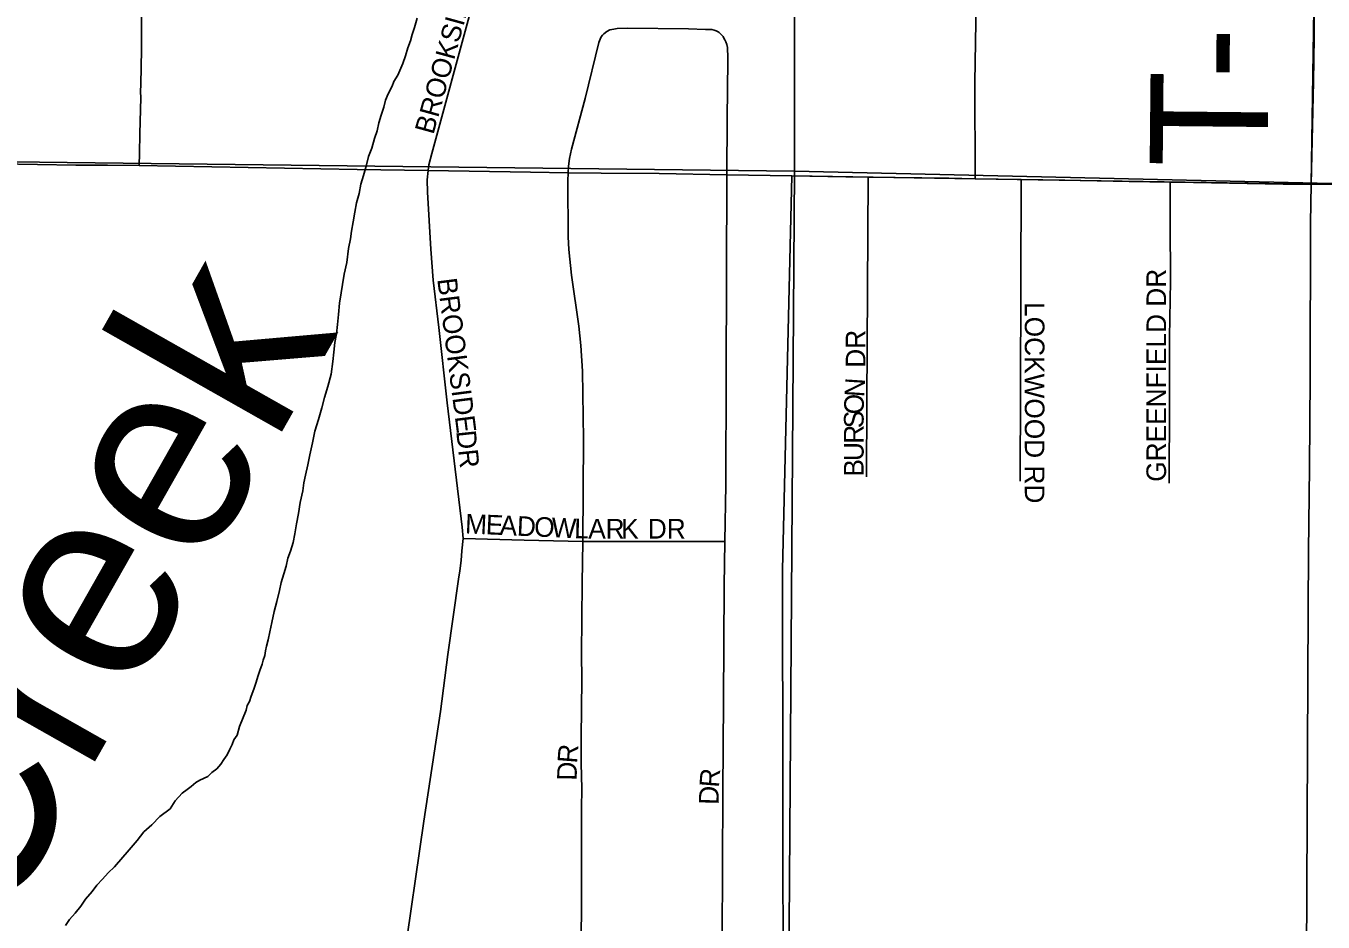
# Model space of a CAD drawing. Extents: x 1587405 to 1714697, y 1028970 to 1155083.
# Drawn here: x 1654205 to 1657507, y 1101017 to 1103299 of the extents above; entities that cross this region are included whole.
import ezdxf

# ---------------------------------------------------------------- set-up
doc = ezdxf.new("R2010")
doc.units = 0
for name, color, linetype in [('GM_X_City_Street', 7, 'Continuous'), ('GM_X_City_Street_Text', 7, 'Continuous'), ('GM_X_Corporation', 7, 'Continuous'), ('GM_X_County_Road', 7, 'Continuous'), ('GM_X_Minor_River', 7, 'Continuous'), ('GM_X_Minor_River_Text', 7, 'Continuous'), ('GM_X_Section', 7, 'Continuous'), ('GM_X_Township_Road', 7, 'Continuous'), ('GM_X_Township_Road_Text', 7, 'Continuous'), ('GM_X_Township_Subdivision', 7, 'Continuous'), ('GM_X_Township_Subdivision_Text', 7, 'Continuous')]:
    doc.layers.add(name, color=color, linetype=linetype)

msp = doc.modelspace()

# ---------------------------------------------------------------- linework, layer by layer
at = {"layer": 'GM_X_City_Street'}
for points in [[(1655228.4, 1102931.1), (1655230.8, 1102945.5), (1655238.5, 1102974), (1655336.1, 1103332.1), (1655370.9, 1103463.4), (1655425.8, 1103654.1)], [(1654493.3, 1102943.2), (1654493.8, 1102975.2), (1654494.5, 1103024), (1654497.1, 1103116.4), (1654496.2, 1103130.9), (1654497.5, 1103150.6), (1654499, 1103238), (1654499.3, 1103444)], [(1656621.7, 1102909.9), (1656620.9, 1103156.2), (1656624.4, 1103410.8)], [(1655989.2, 1102920), (1655989.7, 1103063.4), (1655992, 1103211.1), (1655991.6, 1103225.3), (1655991.2, 1103236.2), (1655990.5, 1103243.7), (1655989, 1103251.4), (1655986.4, 1103258.4), (1655984.4, 1103263.6), (1655981.8, 1103268.3), (1655979.9, 1103271.9), (1655976.7, 1103275.7), (1655972.6, 1103279.8), (1655969.7, 1103281.9), (1655966.9, 1103284.1), (1655962, 1103286.6), (1655956.5, 1103288.3), (1655951.2, 1103289.6), (1655948.6, 1103289.9), (1655942.2, 1103290.3), (1655934.5, 1103290.3), (1655891.2, 1103291.8), (1655736.4, 1103293.3), (1655709.8, 1103292.2), (1655701.7, 1103291.2), (1655691.7, 1103288.7), (1655683.7, 1103285.2), (1655676.1, 1103279.1)], [(1655585, 1102925.2), (1655586.2, 1102942.1), (1655589, 1102961.7), (1655593.8, 1102985.2), (1655628.6, 1103114.4), (1655663.1, 1103256.8), (1655666.5, 1103265.7), (1655669.6, 1103271.3), (1655673, 1103275.5), (1655676.1, 1103279.1)], [(1653516.3, 1102952.3), (1653676.5, 1102951.3), (1653922.3, 1102949.4), (1654135.5, 1102948.2), (1654332.1, 1102944.6), (1654412.6, 1102944.6), (1654493.3, 1102943.2)], [(1654493.3, 1102943.2), (1655047.8, 1102933.3), (1655228.4, 1102931.1)], [(1655228.4, 1102931.1), (1655226.4, 1102907.3), (1655226.9, 1102875.7), (1655235.7, 1102730.2), (1655241.9, 1102651.5), (1655256, 1102530.8), (1655277.5, 1102339.2), (1655315.1, 1102022.6), (1655317.6, 1101993.9)], [(1655228.4, 1102931.1), (1655489.3, 1102926.5), (1655585, 1102925.2)], [(1655622.8, 1101985.7), (1655624.6, 1102246.5), (1655621.6, 1102420.1), (1655617.7, 1102485.5), (1655612.3, 1102534.4), (1655593.7, 1102664.2), (1655586.7, 1102729.4), (1655585.2, 1102762.1), (1655584, 1102904.8), (1655585, 1102925.2)], [(1655585, 1102925.2), (1655669.6, 1102924), (1655817.2, 1102923.3), (1655989.2, 1102920)], [(1655984.1, 1101986.2), (1655986.6, 1102130), (1655987.8, 1102409.1), (1655989.2, 1102920)], [(1655989.2, 1102920), (1656154.5, 1102917.2)], [(1655317.6, 1101993.9), (1655314.8, 1101962.3), (1655312.6, 1101937.3), (1655309.3, 1101911.5), (1655306, 1101890.4), (1655278.5, 1101698.4), (1655260.4, 1101552.6), (1655217.7, 1101273.7), (1655164.7, 1100903.6)], [(1655317.6, 1101993.9), (1655473.6, 1101989.8), (1655622.8, 1101985.7)], [(1655614.4, 1100892), (1655618.8, 1101028.2), (1655618.8, 1101142.9), (1655618.8, 1101306.9), (1655619.7, 1101356.1), (1655618.3, 1101421.5), (1655618.4, 1101487), (1655619.9, 1101634.3), (1655619.4, 1101699.8), (1655620.6, 1101880.1), (1655622.8, 1101985.7)], [(1655622.8, 1101985.7), (1655984.1, 1101986.2)], [(1655975.7, 1100887.2), (1655977.3, 1100972), (1655978.9, 1101349.4), (1655980.4, 1101579.1), (1655982.1, 1101873.1), (1655984.1, 1101986.2)]]:
    msp.add_lwpolyline(points, dxfattribs=at)
at = {"layer": 'GM_X_Corporation'}
msp.add_lwpolyline([(1660013.6, 1108132.7), (1659992.5, 1104646), (1659461.1, 1104914.9), (1659349.2, 1104921.4), (1659344, 1103338.8), (1659336.3, 1102861.5), (1658982.8, 1102866.6), (1658983.7, 1102753.2), (1658842.9, 1102872.1), (1658419.8, 1103185), (1658402.9, 1103164.5), (1658418.3, 1103151.6), (1658415.7, 1103129.7), (1658127.5, 1103132.3), (1657841.9, 1103138.8), (1657848.8, 1103552), (1657490.3, 1103777.1), (1657484.7, 1103398.8), (1657477.2, 1102896.2), (1656621.6, 1102909.9), (1656154.5, 1102917.2), (1656130.9, 1101913.7), (1656133.6, 1100208.9)], dxfattribs=at)
at = {"layer": 'GM_X_County_Road'}
for points in [[(1656154.5, 1102917.2), (1656292.4, 1102914.8), (1656349, 1102913.9)], [(1656349, 1102913.9), (1656554.7, 1102911), (1656621.7, 1102909.9)], [(1656621.7, 1102909.9), (1656738.8, 1102907.8)], [(1656738.8, 1102907.8), (1656849.8, 1102905.9), (1657013.6, 1102902.9), (1657118, 1102901.3)], [(1657118, 1102901.3), (1657177.6, 1102900.3), (1657405.2, 1102896.2), (1657477.2, 1102896.2)], [(1657477.2, 1102896.2), (1657650.8, 1102893.4), (1657814.2, 1102889.6), (1658173.8, 1102884.2), (1658468.1, 1102878.7), (1658746, 1102871.9), (1658806.3, 1102872), (1658842.9, 1102872.1)]]:
    msp.add_lwpolyline(points, dxfattribs=at)
at = {"layer": 'GM_X_Minor_River'}
for points in [[(1655200.8, 1103318.8), (1655194.2, 1103294.9), (1655187.9, 1103276.9), (1655183.5, 1103261), (1655177.1, 1103243.1), (1655170.7, 1103223.1), (1655164.3, 1103203.2), (1655151.7, 1103173.3), (1655141.3, 1103157.5), (1655137, 1103145.6), (1655126.6, 1103125.7), (1655120.3, 1103109.8), (1655115.9, 1103091.8), (1655109.5, 1103071.9), (1655103, 1103052), (1655098.6, 1103032), (1655092.2, 1103012.1), (1655085.7, 1102988.1), (1655077.2, 1102966.2), (1655070.7, 1102942.3), (1655064.2, 1102918.3), (1655057.7, 1102896.4), (1655053.2, 1102872.4), (1655046.7, 1102848.5), (1655042.2, 1102824.5), (1655037.7, 1102800.5), (1655033.2, 1102776.5), (1655030.8, 1102756.5), (1655026.3, 1102732.5), (1655021.6, 1102696.5), (1655015, 1102666.6), (1655003.4, 1102592.6), (1655000.8, 1102564.5), (1654998.3, 1102538.5), (1654995.8, 1102514.5), (1654991.4, 1102492.5), (1654988.9, 1102468.5), (1654986.4, 1102444.5), (1654981.7, 1102412.5), (1654973, 1102380.5), (1654964.5, 1102352.6), (1654957.9, 1102326.7), (1654949.3, 1102296.8), (1654940.6, 1102266.8), (1654934, 1102236.9), (1654927.4, 1102206.9), (1654922.8, 1102180.9), (1654916.3, 1102155), (1654911.9, 1102135), (1654909.5, 1102115), (1654902.8, 1102085.1), (1654898.3, 1102057.1), (1654893.7, 1102031.1), (1654889.2, 1102005.1), (1654884.7, 1101983.1), (1654878.3, 1101961.2), (1654871.9, 1101943.2), (1654867.5, 1101923.3), (1654861, 1101903.3), (1654854.6, 1101881.4)], [(1654854.6, 1101881.4), (1654850.1, 1101861.4), (1654843.6, 1101833.5), (1654837, 1101807.5), (1654830.4, 1101779.6), (1654825.9, 1101755.6), (1654821.5, 1101735.6), (1654817.2, 1101719.7), (1654814.9, 1101707.7), (1654812.7, 1101695.7), (1654808.4, 1101683.7), (1654806.2, 1101673.8), (1654799.9, 1101657.8), (1654795.5, 1101641.9), (1654791.2, 1101627.9), (1654784.9, 1101610), (1654778.5, 1101592.1), (1654774.2, 1101578.1), (1654768, 1101568.2), (1654765.7, 1101556.2), (1654748.8, 1101514.4), (1654742.3, 1101492.5), (1654734.1, 1101480.6), (1654729.8, 1101468.7), (1654723.6, 1101456.8), (1654717.3, 1101442.8), (1654709, 1101431), (1654700.7, 1101419.1), (1654690.4, 1101407.3), (1654678.2, 1101397.5), (1654668, 1101387.7), (1654647.7, 1101378), (1654637.6, 1101372.2), (1654625.3, 1101362.4), (1654615.1, 1101354.6), (1654602.9, 1101344.8), (1654584.4, 1101325.2), (1654572, 1101305.3), (1654545.5, 1101285.8), (1654525, 1101264.2), (1654504.6, 1101246.5), (1654488.1, 1101224.8), (1654467.5, 1101201.1), (1654430.5, 1101157.8), (1654414.2, 1101142), (1654399.8, 1101126.3), (1654385.4, 1101110.5), (1654373.1, 1101094.7), (1654356.6, 1101075), (1654344.2, 1101057.2), (1654329.8, 1101039.4), (1654315.5, 1101023.6), (1654305.1, 1101007.8)]]:
    msp.add_lwpolyline(points, dxfattribs=at)
at = {"layer": 'GM_X_Section'}
for points in [[(1651041.3, 1108325.5), (1656163.1, 1108222.1), (1656161.5, 1102928.9), (1650963.1, 1102991.2), (1650961.9, 1103051.3)], [(1656163.1, 1108222.1), (1661543.6, 1108095.1), (1661485.6, 1102806.5), (1656161.5, 1102928.9)], [(1656161.5, 1102928.9), (1656123.9, 1097642.2), (1650873.6, 1097703.2), (1650963.1, 1102991.2)], [(1656161.5, 1102928.9), (1661485.6, 1102806.5), (1661429.4, 1097506), (1656123.9, 1097642.2)]]:
    msp.add_lwpolyline(points, close=True, dxfattribs=at)
at = {"layer": 'GM_X_Township_Road'}
for points in [[(1657477.2, 1102896.2), (1657482.6, 1103156.3), (1657484.7, 1103270.5), (1657484.7, 1103345.9)], [(1657469.4, 1101813.1), (1657470.1, 1101961.2), (1657472.2, 1102174.5), (1657474, 1102403.4), (1657475.2, 1102797), (1657477.2, 1102896.2)], [(1657464.2, 1099852.3), (1657464.2, 1099894), (1657464.8, 1100550.2), (1657464.4, 1100747.1), (1657469.4, 1101813.1)]]:
    msp.add_lwpolyline(points, dxfattribs=at)
at = {"layer": 'GM_X_Township_Subdivision'}
for points in [[(1656345.9, 1102341.6), (1656349, 1102913.9)], [(1656736.9, 1102373), (1656738.8, 1102907.8)], [(1657116.1, 1102346.2), (1657116, 1102506.1), (1657118.3, 1102648.7), (1657117.7, 1102799.4), (1657117.9, 1102865.4), (1657118, 1102901.3)], [(1656736.1, 1102140), (1656736.9, 1102373)], [(1656344.8, 1102150.9), (1656345.9, 1102341.6)], [(1657114.9, 1102134.7), (1657116.1, 1102340.5), (1657116.1, 1102346.2)]]:
    msp.add_lwpolyline(points, dxfattribs=at)

# ---------------------------------------------------------------- texts
at = {"layer": 'GM_X_City_Street_Text'}
for s, rotation, p in [('BROOKSIDE', 74.5538, (1655242.1, 1103020.6)), ('BROOKSIDE', 277.3046, (1655251.7, 1102654.1)), ('DR', 276.0168, (1655300.1, 1102266.7)), ('M', 357.4859, (1655322, 1102006.7)), ('E', 357.4908, (1655374.7, 1102004.4)), ('A', 357.4858, (1655409.9, 1102002.8)), ('D', 357.4933, (1655453.9, 1102000.9)), ('O', 357.4858, (1655497.8, 1101999)), ('W', 357.4776, (1655541.8, 1101997)), ('L', 358.5883, (1655600, 1101994.5)), ('A', 359.8912, (1655636.4, 1101993.6)), ('R', 359.9941, (1655680.5, 1101993.5)), ('K', 359.9929, (1655720.1, 1101993.5)), ('DR', 0, (1655788, 1101993.5)), ('R', 85.4299, (1655607.6, 1101419.8)), ('D', 89.0819, (1655607, 1101376.7)), ('R', 85.4784, (1655968.9, 1101358.2)), ('D', 88.492, (1655967.8, 1101314.9))]:
    msp.add_text(s, height=50, rotation=rotation, dxfattribs=at).set_placement(p)
at = {"layer": 'GM_X_Minor_River_Text'}
msp.add_text('Creek', height=500.21, rotation=60.462, dxfattribs=at).set_placement((1654119.8, 1100965.3))
at = {"layer": 'GM_X_Township_Road_Text'}
for s, rotation, p in [('-', 89.4672, (1657367.7, 1103161.9)), ('T', 89.4311, (1657365.5, 1102937.7))]:
    msp.add_text(s, height=300, rotation=rotation, dxfattribs=at).set_placement(p)
at = {"layer": 'GM_X_Township_Subdivision_Text'}
for s, rotation, p in [('GREENFIELD DR', 90, (1657107.4, 1102138.1)), ('LOCKWOOD RD', 270, (1656747.8, 1102595.7)), ('DR', 90, (1656341.8, 1102428.5)), ('N', 86.2164, (1656338.4, 1102352.8)), ('O', 88.6886, (1656337.4, 1102309.4)), ('S', 89.9453, (1656337.4, 1102274.5)), ('R', 89.9703, (1656337.4, 1102234.9)), ('U', 89.9563, (1656337.4, 1102190.9)), ('B', 89.9757, (1656337.3, 1102151.3))]:
    msp.add_text(s, height=50, rotation=rotation, dxfattribs=at).set_placement(p)

doc.saveas('drawing.dxf')
